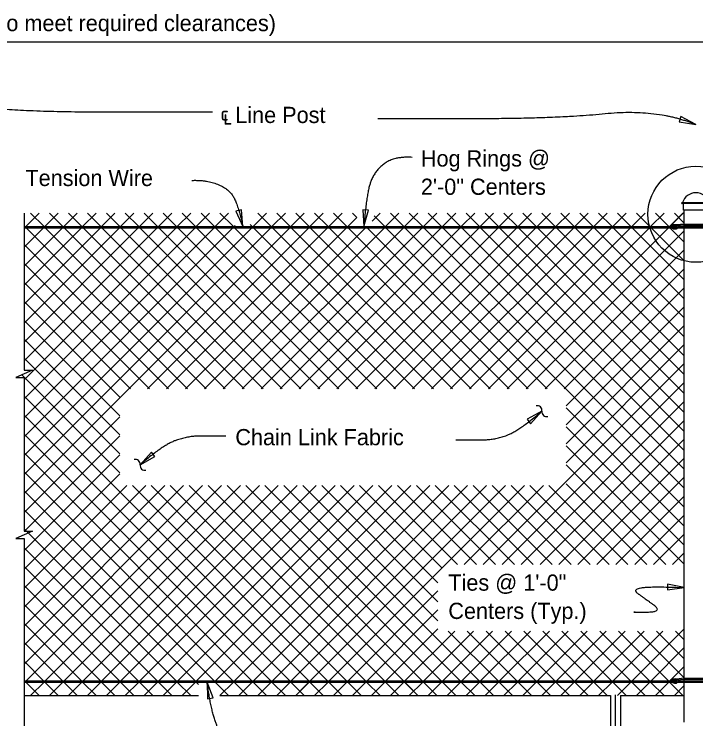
# Model space of a CAD drawing. Extents: x 0 to 41, y -96 to 25.
# Drawn here: x 16.13 to 24.62, y -79.16 to -70.39 of the extents above; entities that cross this region are included whole.
import ezdxf

# ---------------------------------------------------------------- set-up
doc = ezdxf.new("R2010")
doc.units = 0
for name, color, linetype in [('CL_Major', 7, 'Continuous'), ('Dimension', 7, 'Continuous'), ('Miscellaneous', 7, 'Continuous'), ('SteelMisc', 7, 'Continuous'), ('SteelMisc_h', 7, 'Continuous'), ('SupstrConc', 7, 'Continuous'), ('TextStructures', 7, 'Continuous')]:
    doc.layers.add(name, color=color, linetype=linetype)

msp = doc.modelspace()

# ---------------------------------------------------------------- linework, layer by layer
at = {"layer": 'CL_Major'}
msp.add_line((23.6151, -84.4142), (23.6151, -78.8563), dxfattribs=at)
at = {"layer": 'Dimension'}
for points in [[(13.615, -70.732), (15.0787, -70.732), (15.0787, -70.6286), (15.1237, -70.732), (15.1687, -70.8353), (15.1687, -70.732), (28.4596, -70.732)], [(16.252, -72.861), (16.252, -74.8173), (16.3553, -74.8173), (16.252, -74.8623), (16.1487, -74.9073), (16.252, -74.9073), (16.252, -75.8009)], [(16.252, -75.8009), (16.252, -76.8187), (16.3553, -76.8187), (16.252, -76.8637), (16.1487, -76.9087), (16.252, -76.9087), (16.252, -79.113)], [(16.252, -78.863), (16.252, -80.7139), (16.3553, -80.7139), (16.252, -80.7589), (16.1487, -80.8039), (16.252, -80.8039), (16.252, -82.8047)]]:
    msp.add_lwpolyline(points, dxfattribs=at)
for points in [[(24.6151, -71.7592), (24.4287, -71.6599), (24.4064, -71.7268)], [(18.9764, -73.0297), (18.9562, -72.8195), (18.8881, -72.8379)], [(20.4816, -73.0297), (20.5377, -72.8261), (20.4675, -72.819)], [(22.699, -75.3264), (22.5135, -75.4273), (22.5571, -75.4828)], [(17.695, -75.993), (17.8805, -75.892), (17.8369, -75.8365)], [(24.4692, -77.5215), (24.2626, -77.4777), (24.2597, -77.5482)], [(18.5297, -78.6964), (18.5346, -78.9076), (18.6039, -78.8941)]]:
    msp.add_lwpolyline(points, close=True, dxfattribs=at)
msp.add_circle((24.615, -72.8755), 0.5976, dxfattribs=at)
for centre, start, end in [((22.6394, -75.3179), 352.34263, 104.06985), ((22.7576, -75.3338), 172.34263, 284.06985), ((17.6364, -75.9856), 352.34263, 104.06985), ((17.7546, -76.0015), 172.34263, 284.06985)]:
    msp.add_arc(centre, 0.0596, start, end, dxfattribs=at)
for points in [[(18.5966, -71.6049), (17.7933, -71.6049), (16.4039, -71.6049), (15.2225, -71.5103), (14.615, -71.4062)], [(20.6562, -71.683), (21.1029, -71.683), (22.8703, -71.683), (24.1369, -71.56), (24.615, -71.7593)], [(21.0813, -72.1678), (20.8634, -72.1554), (20.6196, -72.3299), (20.5135, -72.6138), (20.4817, -73.0298)], [(18.338, -72.4544), (18.5184, -72.4473), (18.8013, -72.5571), (18.9216, -72.7766), (18.9764, -73.0298)], [(21.6258, -75.6828), (21.8279, -75.6828), (22.1015, -75.6828), (22.4083, -75.5749), (22.6984, -75.3259)], [(18.7638, -75.6366), (18.5661, -75.6366), (18.2925, -75.6366), (17.9858, -75.7445), (17.6956, -75.9934)], [(23.8587, -77.8261), (23.7933, -77.8261), (24.2134, -77.8261), (23.9631, -77.649), (23.826, -77.5463), (24.0365, -77.5038), (24.4692, -77.5215)], [(19.1927, -79.4904), (18.7949, -79.4904), (18.5909, -79.1534), (18.5297, -78.6965)]]:
    msp.add_open_spline(points, degree=2, dxfattribs=at)
at = {"layer": 'Miscellaneous'}
for p, q in [((16.2736, -73.0298), (16.4402, -72.8631)), ((16.3328, -72.8631), (16.4994, -73.0298)), ((16.5093, -73.0298), (16.6759, -72.8631)), ((16.5685, -72.8631), (16.7352, -73.0298)), ((16.745, -73.0298), (16.9116, -72.8631)), ((16.8042, -72.8631), (16.9709, -73.0298)), ((16.9807, -73.0298), (17.1473, -72.8631)), ((17.0399, -72.8631), (17.2066, -73.0298)), ((17.2164, -73.0298), (17.383, -72.8631)), ((17.2756, -72.8631), (17.4423, -73.0298)), ((17.4521, -73.0298), (17.6187, -72.8631)), ((17.5113, -72.8631), (17.678, -73.0298)), ((17.6878, -73.0298), (17.8544, -72.8631)), ((17.747, -72.8631), (17.9137, -73.0298)), ((17.9235, -73.0298), (18.0901, -72.8631)), ((17.9827, -72.8631), (18.1494, -73.0298)), ((18.1592, -73.0298), (18.3258, -72.8631)), ((18.2184, -72.8631), (18.3851, -73.0298)), ((18.3949, -73.0298), (18.5615, -72.8631)), ((18.4541, -72.8631), (18.6208, -73.0298)), ((18.6306, -73.0298), (18.7972, -72.8631)), ((18.6898, -72.8631), (18.8565, -73.0298)), ((19.102, -73.0298), (19.2687, -72.8631)), ((19.1612, -72.8631), (19.3279, -73.0298)), ((19.3377, -73.0298), (19.5044, -72.8631)), ((19.3969, -72.8631), (19.5636, -73.0298)), ((19.5734, -73.0298), (19.7401, -72.8631)), ((19.6326, -72.8631), (19.7993, -73.0298)), ((19.8091, -73.0298), (19.9758, -72.8631)), ((19.8683, -72.8631), (20.035, -73.0298)), ((20.0448, -73.0298), (20.2115, -72.8631)), ((20.104, -72.8631), (20.2707, -73.0298)), ((20.3397, -72.8631), (20.3934, -72.9168)), ((20.5829, -72.9631), (20.6829, -72.8631)), ((20.7519, -73.0298), (20.9186, -72.8631)), ((20.8111, -72.8631), (20.9778, -73.0298)), ((20.9876, -73.0298), (21.1543, -72.8631)), ((21.0468, -72.8631), (21.2135, -73.0298)), ((21.2233, -73.0298), (21.39, -72.8631)), ((21.2825, -72.8631), (21.4492, -73.0298)), ((21.459, -73.0298), (21.6257, -72.8631)), ((21.5182, -72.8631), (21.6849, -73.0298)), ((21.6947, -73.0298), (21.8614, -72.8631)), ((21.7539, -72.8631), (21.9206, -73.0298)), ((21.9304, -73.0298), (22.0971, -72.8631)), ((21.9896, -72.8631), (22.1563, -73.0298)), ((22.1661, -73.0298), (22.3328, -72.8631)), ((22.2253, -72.8631), (22.392, -73.0298)), ((22.2674, -75.0498), (24.4692, -72.848)), ((22.4018, -73.0298), (22.5685, -72.8631)), ((22.461, -72.8631), (22.6277, -73.0298)), ((22.6375, -73.0298), (22.8042, -72.8631)), ((22.6967, -72.8631), (22.8634, -73.0298)), ((22.8732, -73.0298), (23.0399, -72.8631)), ((22.9324, -72.8631), (23.0991, -73.0298)), ((23.1089, -73.0298), (23.2756, -72.8631)), ((23.1681, -72.8631), (23.3348, -73.0298)), ((23.3446, -73.0298), (23.5113, -72.8631)), ((23.4038, -72.8631), (23.5705, -73.0298)), ((23.5803, -73.0298), (23.747, -72.8631)), ((23.6396, -72.8631), (23.8062, -73.0298)), ((23.816, -73.0298), (23.9827, -72.8631)), ((23.8753, -72.8631), (24.0419, -73.0298)), ((24.0517, -73.0298), (24.2184, -72.8631)), ((24.111, -72.8631), (24.2776, -73.0298)), ((24.2874, -73.0298), (24.4541, -72.8631)), ((24.3467, -72.8631), (24.4692, -72.9857)), ((20.2805, -73.0298), (20.3934, -72.9168)), ((20.6086, -72.8962), (20.7421, -73.0298)), ((16.252, -76.3512), (19.5586, -73.0445)), ((16.252, -75.8798), (19.0872, -73.0445)), ((16.252, -74.937), (18.1444, -73.0445)), ((16.252, -75.4084), (18.6158, -73.0445)), ((16.252, -76.1155), (19.3229, -73.0445)), ((16.252, -75.6441), (18.8515, -73.0445)), ((16.252, -75.1727), (18.3801, -73.0445)), ((16.252, -74.7013), (17.9087, -73.0445)), ((16.252, -74.4655), (17.673, -73.0445)), ((16.252, -73.9941), (17.2016, -73.0445)), ((16.252, -74.2298), (17.4373, -73.0445)), ((16.252, -73.5227), (16.7302, -73.0445)), ((16.252, -73.0513), (16.2588, -73.0445)), ((16.252, -73.7584), (16.9659, -73.0445)), ((16.252, -73.287), (16.4945, -73.0445)), ((16.2785, -73.0445), (18.2838, -75.0498)), ((16.5142, -73.0445), (18.5195, -75.0498)), ((16.7499, -73.0445), (18.7552, -75.0498)), ((16.9856, -73.0445), (18.9909, -75.0498)), ((17.2213, -73.0445), (19.2266, -75.0498)), ((17.457, -73.0445), (19.4623, -75.0498)), ((17.6927, -73.0445), (19.698, -75.0498)), ((17.7891, -75.0498), (19.7943, -73.0445)), ((17.9284, -73.0445), (19.9337, -75.0498)), ((18.0248, -75.0498), (20.03, -73.0445)), ((18.1641, -73.0445), (20.1694, -75.0498)), ((18.2605, -75.0498), (20.2657, -73.0445)), ((18.3998, -73.0445), (20.4051, -75.0498)), ((18.4962, -75.0498), (20.5014, -73.0445)), ((18.6355, -73.0445), (20.6408, -75.0498)), ((18.7319, -75.0498), (20.7372, -73.0445)), ((18.8663, -73.0298), (18.8813, -73.0148)), ((18.8712, -73.0445), (20.8765, -75.0498)), ((18.9676, -75.0498), (20.9729, -73.0445)), ((19.065, -73.0026), (19.0922, -73.0298)), ((19.1069, -73.0445), (21.1122, -75.0498)), ((19.2033, -75.0498), (21.2086, -73.0445)), ((19.3426, -73.0445), (21.3479, -75.0498)), ((19.439, -75.0498), (21.4443, -73.0445)), ((19.5783, -73.0445), (21.5836, -75.0498)), ((19.6747, -75.0498), (21.68, -73.0445)), ((19.814, -73.0445), (21.8193, -75.0498)), ((19.9104, -75.0498), (21.9157, -73.0445)), ((20.0497, -73.0445), (22.055, -75.0498)), ((20.1461, -75.0498), (22.1514, -73.0445)), ((20.2854, -73.0445), (22.2907, -75.0498)), ((20.3818, -75.0498), (22.3871, -73.0445)), ((20.5211, -73.0445), (22.5264, -75.0498)), ((20.6175, -75.0498), (22.6228, -73.0445)), ((20.7568, -73.0445), (22.7621, -75.0498)), ((20.8532, -75.0498), (22.8585, -73.0445)), ((20.9925, -73.0445), (24.4692, -76.5212)), ((21.0889, -75.0498), (23.0942, -73.0445)), ((21.2282, -73.0445), (24.4692, -76.2855)), ((21.3246, -75.0498), (23.3299, -73.0445)), ((21.4639, -73.0445), (24.4692, -76.0498)), ((21.5603, -75.0498), (23.5656, -73.0445)), ((21.6996, -73.0445), (24.4692, -75.8141)), ((21.796, -75.0498), (23.8013, -73.0445)), ((21.9353, -73.0445), (24.4692, -75.5784)), ((22.0317, -75.0498), (24.037, -73.0445)), ((22.1711, -73.0445), (24.4692, -75.3427)), ((22.4068, -73.0445), (24.4692, -75.107)), ((22.6425, -73.0445), (24.4692, -74.8713)), ((22.8782, -73.0445), (24.4692, -74.6356)), ((23.1139, -73.0445), (24.4692, -74.3999)), ((23.3496, -73.0445), (24.4692, -74.1642)), ((23.5853, -73.0445), (24.4692, -73.9285)), ((23.821, -73.0445), (24.4692, -73.6928)), ((24.0567, -73.0445), (24.4692, -73.4571)), ((24.2924, -73.0445), (24.4692, -73.2214)), ((22.5031, -75.0498), (24.4692, -73.0837)), ((16.252, -73.2537), (18.0481, -75.0498)), ((22.7388, -75.0498), (24.4692, -73.3194)), ((16.252, -73.4894), (17.8124, -75.0498)), ((22.9745, -75.0498), (24.4692, -73.5551)), ((16.252, -73.7251), (17.5767, -75.0498)), ((22.9985, -75.2615), (24.4692, -73.7908)), ((16.252, -73.9608), (17.4417, -75.1505)), ((22.9985, -75.4972), (24.4692, -74.0265)), ((16.252, -74.1965), (17.4417, -75.3862)), ((22.9985, -75.7329), (24.4692, -74.2622)), ((16.252, -74.4322), (17.4417, -75.6219)), ((22.9985, -75.9686), (24.4692, -74.4979)), ((16.252, -74.6679), (17.4417, -75.8576)), ((21.9677, -77.2351), (24.4692, -74.7336)), ((16.2232, -74.8749), (17.4417, -76.0933)), ((22.2034, -77.2351), (24.4692, -74.9693)), ((16.252, -75.1393), (19.7943, -78.6817)), ((22.4391, -77.2351), (24.4692, -75.205)), ((22.9985, -75.2862), (24.4692, -76.7569)), ((16.252, -75.375), (19.5586, -78.6817)), ((16.252, -76.5869), (17.4417, -75.3972)), ((22.6748, -77.2351), (24.4692, -75.4407)), ((22.9985, -75.5219), (24.4692, -76.9926)), ((16.252, -75.6107), (19.3229, -78.6817)), ((16.2558, -76.8187), (17.4417, -75.6329)), ((22.9105, -77.2351), (24.4692, -75.6764)), ((22.9985, -75.7576), (24.4692, -77.2283)), ((16.252, -75.8464), (19.0872, -78.6817)), ((16.252, -77.0583), (17.4417, -75.8686)), ((23.1462, -77.2351), (24.4692, -75.9121)), ((22.9985, -75.9933), (24.2403, -77.2351)), ((16.252, -76.0821), (18.8515, -78.6817)), ((16.252, -77.294), (17.4417, -76.1043)), ((23.3819, -77.2351), (24.4692, -76.1478)), ((16.252, -78.2368), (18.2378, -76.251)), ((16.252, -77.7654), (17.7664, -76.251)), ((16.252, -77.5297), (17.5307, -76.251)), ((16.252, -78.0011), (18.0021, -76.251)), ((16.252, -78.4725), (18.4735, -76.251)), ((16.2785, -78.6817), (18.7092, -76.251)), ((16.5142, -78.6817), (18.9449, -76.251)), ((16.7499, -78.6817), (19.1806, -76.251)), ((16.9856, -78.6817), (19.4163, -76.251)), ((17.2213, -78.6817), (19.652, -76.251)), ((17.457, -78.6817), (19.8877, -76.251)), ((17.5994, -76.251), (20.03, -78.6817)), ((17.6927, -78.6817), (20.1234, -76.251)), ((17.8351, -76.251), (20.2657, -78.6817)), ((17.9284, -78.6817), (20.3591, -76.251)), ((18.0708, -76.251), (20.5014, -78.6817)), ((18.1641, -78.6817), (20.5948, -76.251)), ((18.3065, -76.251), (20.7372, -78.6817)), ((18.3998, -78.6817), (20.8305, -76.251)), ((18.5422, -76.251), (21.0907, -78.7995)), ((18.6355, -78.6817), (21.0662, -76.251)), ((18.7779, -76.251), (21.2086, -78.6817)), ((18.8712, -78.6817), (21.3019, -76.251)), ((19.0136, -76.251), (21.4443, -78.6817)), ((19.1069, -78.6817), (21.5376, -76.251)), ((19.2493, -76.251), (21.68, -78.6817)), ((19.3426, -78.6817), (21.7733, -76.251)), ((19.485, -76.251), (21.9157, -78.6817)), ((19.5783, -78.6817), (22.009, -76.251)), ((19.6962, -78.7995), (22.2447, -76.251)), ((19.7207, -76.251), (21.4039, -77.9342)), ((19.9564, -76.251), (21.4039, -77.6985)), ((20.0497, -78.6817), (22.4804, -76.251)), ((20.1921, -76.251), (21.4039, -77.4628)), ((20.4278, -76.251), (21.4541, -77.2773)), ((20.6635, -76.251), (21.6476, -77.2351)), ((20.8992, -76.251), (21.8833, -77.2351)), ((21.1349, -76.251), (22.119, -77.2351)), ((21.3706, -76.251), (22.3547, -77.2351)), ((21.6063, -76.251), (22.5904, -77.2351)), ((21.732, -77.2351), (22.7161, -76.251)), ((21.842, -76.251), (22.8261, -77.2351)), ((22.0777, -76.251), (23.0618, -77.2351)), ((22.3134, -76.251), (23.2975, -77.2351)), ((22.5491, -76.251), (23.5332, -77.2351)), ((22.7848, -76.251), (23.7689, -77.2351)), ((22.9985, -76.229), (24.0046, -77.2351)), ((16.252, -76.3178), (18.6158, -78.6817)), ((23.6176, -77.2351), (24.4692, -76.3835)), ((16.252, -76.5535), (18.3801, -78.6817)), ((23.8533, -77.2351), (24.4692, -76.6192)), ((16.252, -76.7892), (18.1444, -78.6817)), ((24.089, -77.2351), (24.4692, -76.8549)), ((16.252, -77.0249), (17.9087, -78.6817)), ((24.3247, -77.2351), (24.4692, -77.0906)), ((16.252, -77.2606), (17.673, -78.6817)), ((16.252, -77.4963), (17.4373, -78.6817)), ((20.2854, -78.6817), (21.4039, -77.5632)), ((16.252, -77.732), (17.2016, -78.6817)), ((20.5211, -78.6817), (21.4039, -77.7989)), ((16.252, -77.9677), (16.9659, -78.6817)), ((20.7568, -78.6817), (21.4039, -78.0346)), ((23.821, -78.6817), (24.4692, -78.0334)), ((20.9925, -78.6817), (21.6122, -78.0621)), ((21.2282, -78.6817), (21.8479, -78.0621)), ((21.4639, -78.6817), (22.0836, -78.0621)), ((21.5318, -78.0621), (22.1514, -78.6817)), ((21.6996, -78.6817), (22.3193, -78.0621)), ((21.7675, -78.0621), (22.3871, -78.6817)), ((21.9353, -78.6817), (22.555, -78.0621)), ((22.0032, -78.0621), (22.6228, -78.6817)), ((22.1711, -78.6817), (22.7907, -78.0621)), ((22.2389, -78.0621), (22.8585, -78.6817)), ((22.4068, -78.6817), (23.0264, -78.0621)), ((22.4746, -78.0621), (23.0942, -78.6817)), ((22.6425, -78.6817), (23.2621, -78.0621)), ((22.7103, -78.0621), (23.3299, -78.6817)), ((22.8782, -78.6817), (23.4978, -78.0621)), ((22.946, -78.0621), (23.5656, -78.6817)), ((23.1139, -78.6817), (23.7335, -78.0621)), ((23.1817, -78.0621), (23.8013, -78.6817)), ((23.3496, -78.6817), (23.9692, -78.0621)), ((23.4174, -78.0621), (24.037, -78.6817)), ((23.5853, -78.6817), (24.2049, -78.0621)), ((23.6531, -78.0621), (24.2727, -78.6817)), ((23.8888, -78.0621), (24.4692, -78.6425)), ((24.1245, -78.0621), (24.4692, -78.4068)), ((24.3602, -78.0621), (24.4692, -78.1711)), ((16.252, -78.2034), (16.7302, -78.6817)), ((24.0567, -78.6817), (24.4692, -78.2691)), ((16.252, -78.4391), (16.4945, -78.6817)), ((24.3083, -78.6657), (24.4692, -78.5048)), ((16.2736, -78.6964), (16.4402, -78.8631)), ((16.3328, -78.8631), (16.4994, -78.6964)), ((16.5093, -78.6964), (16.6759, -78.8631)), ((16.5685, -78.8631), (16.7352, -78.6964)), ((16.745, -78.6964), (16.9116, -78.8631)), ((16.8042, -78.8631), (16.9709, -78.6964)), ((16.9807, -78.6964), (17.1473, -78.8631)), ((17.0399, -78.8631), (17.2066, -78.6964)), ((17.2164, -78.6964), (17.383, -78.8631)), ((17.2756, -78.8631), (17.4423, -78.6964)), ((17.4521, -78.6964), (17.6187, -78.8631)), ((17.5113, -78.8631), (17.678, -78.6964)), ((17.6878, -78.6964), (17.8544, -78.8631)), ((17.747, -78.8631), (17.9137, -78.6964)), ((17.9235, -78.6964), (18.0901, -78.8631)), ((17.9827, -78.8631), (18.1494, -78.6964)), ((18.1592, -78.6964), (18.3258, -78.8631)), ((18.2184, -78.8631), (18.3851, -78.6964)), ((18.3949, -78.6964), (18.424, -78.7255)), ((18.6306, -78.6964), (18.7972, -78.8631)), ((18.6898, -78.8631), (18.8565, -78.6964)), ((18.8663, -78.6964), (19.0329, -78.8631)), ((18.9255, -78.8631), (19.0922, -78.6964)), ((19.102, -78.6964), (19.2687, -78.8631)), ((19.1612, -78.8631), (19.3279, -78.6964)), ((19.3377, -78.6964), (19.5044, -78.8631)), ((19.3969, -78.8631), (19.5636, -78.6964)), ((19.5734, -78.6964), (19.7401, -78.8631)), ((19.6326, -78.8631), (19.7993, -78.6964)), ((19.8091, -78.6964), (19.9758, -78.8631)), ((19.8683, -78.8631), (20.035, -78.6964)), ((20.0448, -78.6964), (20.2115, -78.8631)), ((20.104, -78.8631), (20.2707, -78.6964)), ((20.2805, -78.6964), (20.4472, -78.8631)), ((20.3397, -78.8631), (20.5064, -78.6964)), ((20.5162, -78.6964), (20.6829, -78.8631)), ((20.5754, -78.8631), (20.7421, -78.6964)), ((20.7519, -78.6964), (20.9186, -78.8631)), ((20.8111, -78.8631), (20.9778, -78.6964)), ((20.9876, -78.6964), (21.1543, -78.8631)), ((21.0468, -78.8631), (21.2135, -78.6964)), ((21.2233, -78.6964), (21.39, -78.8631)), ((21.2825, -78.8631), (21.4492, -78.6964)), ((21.459, -78.6964), (21.6257, -78.8631)), ((21.5182, -78.8631), (21.6849, -78.6964)), ((21.6947, -78.6964), (21.8614, -78.8631)), ((21.7539, -78.8631), (21.9206, -78.6964)), ((21.9304, -78.6964), (22.0971, -78.8631)), ((21.9896, -78.8631), (22.1563, -78.6964)), ((22.1661, -78.6964), (22.3328, -78.8631)), ((22.2253, -78.8631), (22.392, -78.6964)), ((22.4018, -78.6964), (22.5685, -78.8631)), ((22.461, -78.8631), (22.6277, -78.6964)), ((22.6375, -78.6964), (22.8042, -78.8631)), ((22.6967, -78.8631), (22.8634, -78.6964)), ((22.8732, -78.6964), (23.0399, -78.8631)), ((22.9324, -78.8631), (23.0991, -78.6964)), ((23.1089, -78.6964), (23.2756, -78.8631)), ((23.1681, -78.8631), (23.3348, -78.6964)), ((23.3446, -78.6964), (23.5113, -78.8631)), ((23.4038, -78.8631), (23.5705, -78.6964)), ((23.5803, -78.6964), (23.747, -78.8631)), ((23.6396, -78.8631), (23.8062, -78.6964)), ((23.816, -78.6964), (23.9827, -78.8631)), ((23.8753, -78.8631), (24.0419, -78.6964)), ((24.0517, -78.6964), (24.2184, -78.8631)), ((24.111, -78.8631), (24.2776, -78.6964)), ((24.2874, -78.6964), (24.4541, -78.8631)), ((24.2924, -78.6817), (24.296, -78.6781)), ((24.3467, -78.8631), (24.4692, -78.7405))]:
    msp.add_line(p, q, dxfattribs=at)
at = {"layer": 'SteelMisc'}
for p, q in [((24.4427, -72.7311), (24.7873, -72.7311)), ((24.7873, -72.7434), (24.4427, -72.7434)), ((24.461, -72.8231), (24.461, -72.7434)), ((24.7691, -72.8231), (24.461, -72.8231)), ((24.4692, -79.1982), (24.4692, -72.8231)), ((16.252, -73.0298), (24.2941, -73.0298)), ((16.252, -73.0445), (24.3207, -73.0445)), ((24.304, -73.0298), (24.3172, -73.0298)), ((24.4692, -72.9972), (24.3743, -73.0082)), ((24.4692, -73.0117), (24.3766, -73.0212)), ((24.3856, -73.0445), (24.4692, -73.0445)), ((24.387, -73.0298), (24.4692, -73.0298)), ((24.4692, -72.9972), (24.7604, -72.9955)), ((24.4692, -73.0117), (24.7604, -73.01)), ((24.4692, -78.6491), (24.3743, -78.6602)), ((24.4692, -78.6636), (24.3766, -78.6731)), ((24.4692, -78.6491), (24.7604, -78.6474)), ((24.4692, -78.6636), (24.7604, -78.6619)), ((16.252, -78.6817), (24.2941, -78.6817)), ((16.252, -78.6964), (24.3207, -78.6964)), ((24.304, -78.6817), (24.3172, -78.6817)), ((24.3856, -78.6964), (24.4692, -78.6964)), ((24.387, -78.6817), (24.4692, -78.6817))]:
    msp.add_line(p, q, dxfattribs=at)
msp.add_arc((24.4429, -72.7374), 0.00613, 91.1647, 268.8353, dxfattribs=at)
for centre, major_axis, ratio, start_param, end_param in [((24.6157, -72.7722), (0.1711, 0), 0.957868, 0.252602, 2.888574), ((24.3283, -73.044), (0.0373, 0), 0.957868, 1.486836, 3.108042), ((24.3494, -73.0837), (-0.0724, 0), 0.957868, 5.162149, 5.652106), ((24.3419, -73.0321), (-0.0249, 0), 0.957868, 6.009018, 7.089857), ((24.3408, -73.0296), (0.023, 0), 0.957868, 1.29026, 2.970541), ((24.3433, -73.0361), (0.0231, 0), 0.957868, 3.779554, 4.879821), ((24.3595, -73.0349), (0.0295, 0), 0.957868, 1.220941, 4.039556), ((24.373, -73.0331), (-0.0303, -0.0108), 0.724765, 4.35367, 6.324556), ((24.3494, -73.0417), (0.0206, -0.0021), 0.798607, 4.32653, 5.220153), ((24.3629, -73.0417), (0.0206, -0.0021), 0.798607, 3.333154, 5.220153), ((24.3697, -73.0372), (-0.0139, 0), 0.957868, 5.22362, 6.905413), ((24.364, -73.0396), (-0.00795, 0), 0.957868, 6.140374, 9.314262), ((24.3781, -73.0461), (-0.0259, 0), 0.957868, 4.777514, 5.62749), ((24.3624, -73.0338), (0.0119, 0), 0.957868, 5.725876, 7.416677), ((24.3555, -73.023), (0.0391, 0), 0.957868, 5.082588, 5.41974), ((24.3624, -73.0338), (0.0119, 0), 0.957868, 5.639684, 5.723117), ((24.3626, -73.035), (0.0251, 0), 0.957868, 5.531357, 6.227833), ((24.3626, -73.035), (0.0251, 0), 0.957868, 0.407687, 0.609214), ((24.3283, -78.6959), (0.0373, 0), 0.957868, 1.486836, 3.108042), ((24.3408, -78.6815), (0.023, 0), 0.957868, 1.29026, 2.970541), ((24.3595, -78.6868), (0.0295, 0), 0.957868, 1.220941, 4.039556), ((24.373, -78.6851), (-0.0303, -0.0108), 0.724765, 4.35367, 6.324556), ((24.3494, -78.7356), (-0.0724, 0), 0.957868, 5.162149, 5.652106), ((24.3419, -78.684), (-0.0249, 0), 0.957868, 6.009018, 7.089857), ((24.3433, -78.688), (0.0231, 0), 0.957868, 3.779554, 4.879821), ((24.3494, -78.6937), (0.0206, -0.0021), 0.798607, 4.32653, 5.220153), ((24.3629, -78.6937), (0.0206, -0.0021), 0.798607, 3.333154, 5.220153), ((24.3697, -78.6891), (-0.0139, 0), 0.957868, 5.22362, 6.905413), ((24.364, -78.6915), (-0.00795, 0), 0.957868, 6.140374, 9.314262), ((24.3781, -78.698), (-0.0259, 0), 0.957868, 4.777514, 5.62749), ((24.3624, -78.6857), (0.0119, 0), 0.957868, 5.725876, 7.416677), ((24.3555, -78.6749), (0.0391, 0), 0.957868, 5.082588, 5.41974), ((24.3624, -78.6857), (0.0119, 0), 0.957868, 5.639684, 5.723117), ((24.3626, -78.687), (0.0251, 0), 0.957868, 5.531357, 6.227833), ((24.3626, -78.687), (0.0251, 0), 0.957868, 0.407687, 0.609214)]:
    msp.add_ellipse(centre, major_axis=major_axis, ratio=ratio, start_param=start_param, end_param=end_param, dxfattribs=at)
at = {"layer": 'SteelMisc_h'}
for p, q in [((24.4692, -73.0298), (24.7609, -73.0298)), ((24.4692, -73.0445), (24.7609, -73.0445)), ((24.4692, -78.6817), (24.7609, -78.6817)), ((24.4692, -78.6964), (24.7609, -78.6964))]:
    msp.add_line(p, q, dxfattribs=at)
at = {"layer": 'SupstrConc'}
for p, q in [((16.252, -78.8631), (18.424, -78.8631)), ((18.6879, -78.8631), (23.5538, -78.8631)), ((23.5538, -78.8631), (23.5538, -83.3844)), ((23.6763, -78.8631), (23.6763, -82.1964)), ((23.6763, -78.8631), (24.4692, -78.8631))]:
    msp.add_line(p, q, dxfattribs=at)

# ---------------------------------------------------------------- texts
at = {"layer": 'Dimension'}
for s, p in [('Hog Rings @ ', (21.1911, -72.2821)), ('2\'-0" Centers', (21.1911, -72.6341)), ('Ties @ 1\'-0" ', (21.5326, -77.5601)), ('Centers (Typ.)', (21.5326, -77.9121))]:
    msp.add_text(s, height=0.2016, dxfattribs=at).set_placement(p)
at = {"layer": 'TextStructures'}
for s, p in [('Equal Spaces @ 10\'-0" Max. (Posts may be shifted minimally to meet required clearances)', (8.5826, -70.5974)), ('℄ Line Post', (18.6958, -71.7406)), ('Tension Wire', (16.268, -72.5249)), ('Chain Link Fabric', (18.8811, -75.7502))]:
    msp.add_text(s, height=0.2016, dxfattribs=at).set_placement(p)

doc.saveas('drawing.dxf')
